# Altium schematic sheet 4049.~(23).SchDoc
size A4
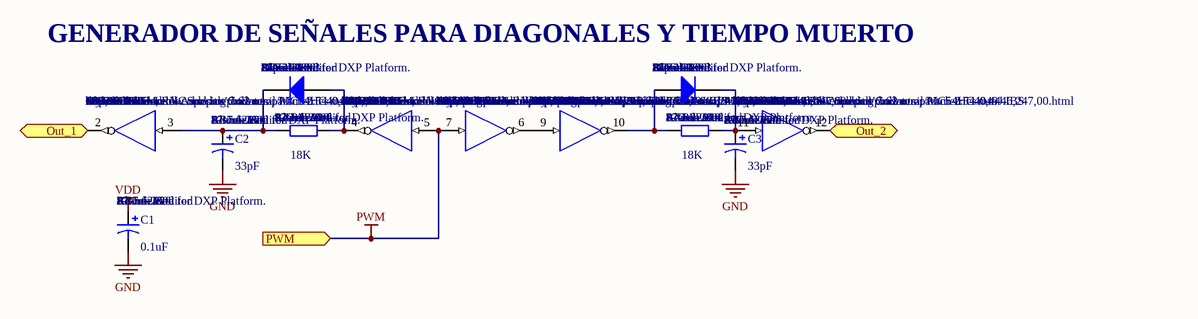
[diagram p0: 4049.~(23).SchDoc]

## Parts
C1  value 0.1uF  Published: 8-Jun-2000  LatestRevisionDate: 17-Jul-2002  LatestRevisionNote: Re-released for DXP Platform.  PackageReference: RB7.6-15  Publisher: Altium Limited  [CAPPR2.5-6.3X5]  (hidden comment: Cap Pol1)
C2  value 33pF  Published: 8-Jun-2000  LatestRevisionDate: 17-Jul-2002  LatestRevisionNote: Re-released for DXP Platform.  PackageReference: RB7.6-15  Publisher: Altium Limited  [CAPPR2.5-6.3X5]  (hidden comment: Cap Pol1)
C3  value 33pF  Published: 8-Jun-2000  LatestRevisionDate: 17-Jul-2002  LatestRevisionNote: Re-released for DXP Platform.  PackageReference: RB7.6-15  Publisher: Altium Limited  [CAPPR2.5-6.3X5]  (hidden comment: Cap Pol1)
D1  Published: 8-Jun-2000  LatestRevisionDate: 17-Jul-2002  LatestRevisionNote: Re-released for DXP Platform.  PackageDocument: Sep-1996  PackageReference: SMC  Publisher: Altium Limited  Code_JEDEC: DO-214-AB  [DO-204AL]  (hidden comment: Diode)
D2  Published: 8-Jun-2000  LatestRevisionDate: 17-Jul-2002  LatestRevisionNote: Re-released for DXP Platform.  PackageDocument: Sep-1996  PackageReference: SMC  Publisher: Altium Limited  Code_JEDEC: DO-214-AB  [DO-204AL]  (hidden comment: Diode)
R1  value 18K  Published: 8-Jun-2000  LatestRevisionDate: 17-Jul-2002  LatestRevisionNote: Re-released for DXP Platform.  PackageReference: AXIAL-0.4  Publisher: Altium Limited  [AXIAL-0.3]  (hidden comment: Res2)
R2  value 18K  Published: 8-Jun-2000  LatestRevisionDate: 17-Jul-2002  LatestRevisionNote: Re-released for DXP Platform.  PackageReference: AXIAL-0.4  Publisher: Altium Limited  [AXIAL-0.3]  (hidden comment: Res2)
U1  Published: 17-Jul-2002  LatestRevisionDate: 06-Jun-2005  LatestRevisionNote: Stylized 3D Model Added  DatasheetVersion: 1989  Publisher: Altium Limited  PackageDescription: DIP; 16 Leads; Row Spacing 7.62 mm; Pitch 2.54 mm  Note: Pins 13 & 16 are NC and not drawn.  Code_JEDEC: MS-001-BB  ComponentLink1Description: Manufacturer Link  ComponentLink2Description: Ibis Model  [620-09]  (hidden comment: MC54HC4049J)  (parts A,B,C,D,E of 6)

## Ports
Out_1 (out), Out_2 (out), PWM (in)

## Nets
GND: C1.2 C2.2 C3.2 U1.8(GND)
PWM: U1.5(A) U1.7(A) ; port PWM
VDD: C1.1 U1.1(VDD)
Out_1: U1.2(Y) ; port Out_1
Out_2: U1.12(Y) ; port Out_2
NetC2_1: C2.1 D1.2(K) R1.1 U1.3(A)
NetC3_1: C3.1 D2.2(K) R2.2 U1.11(A)
NetD1_1: D1.1(A) R1.2 U1.4(Y)
NetD2_1: D2.1(A) R2.1 U1.10(Y)
NetU1_6: U1.6(Y) U1.9(A)

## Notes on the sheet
- GENERADOR DE SEÑALES PARA DIAGONALES Y TIEMPO MUERTO

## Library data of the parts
C1-C3 = Cap Pol1: Polarized Capacitor (Radial)
D1 D2 = Diode: 1N4148
R1 R2 = Res2: Resistor
U1 = MC54HC4049J: Hex Inverting Buffer/Logic-Level Down Converter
